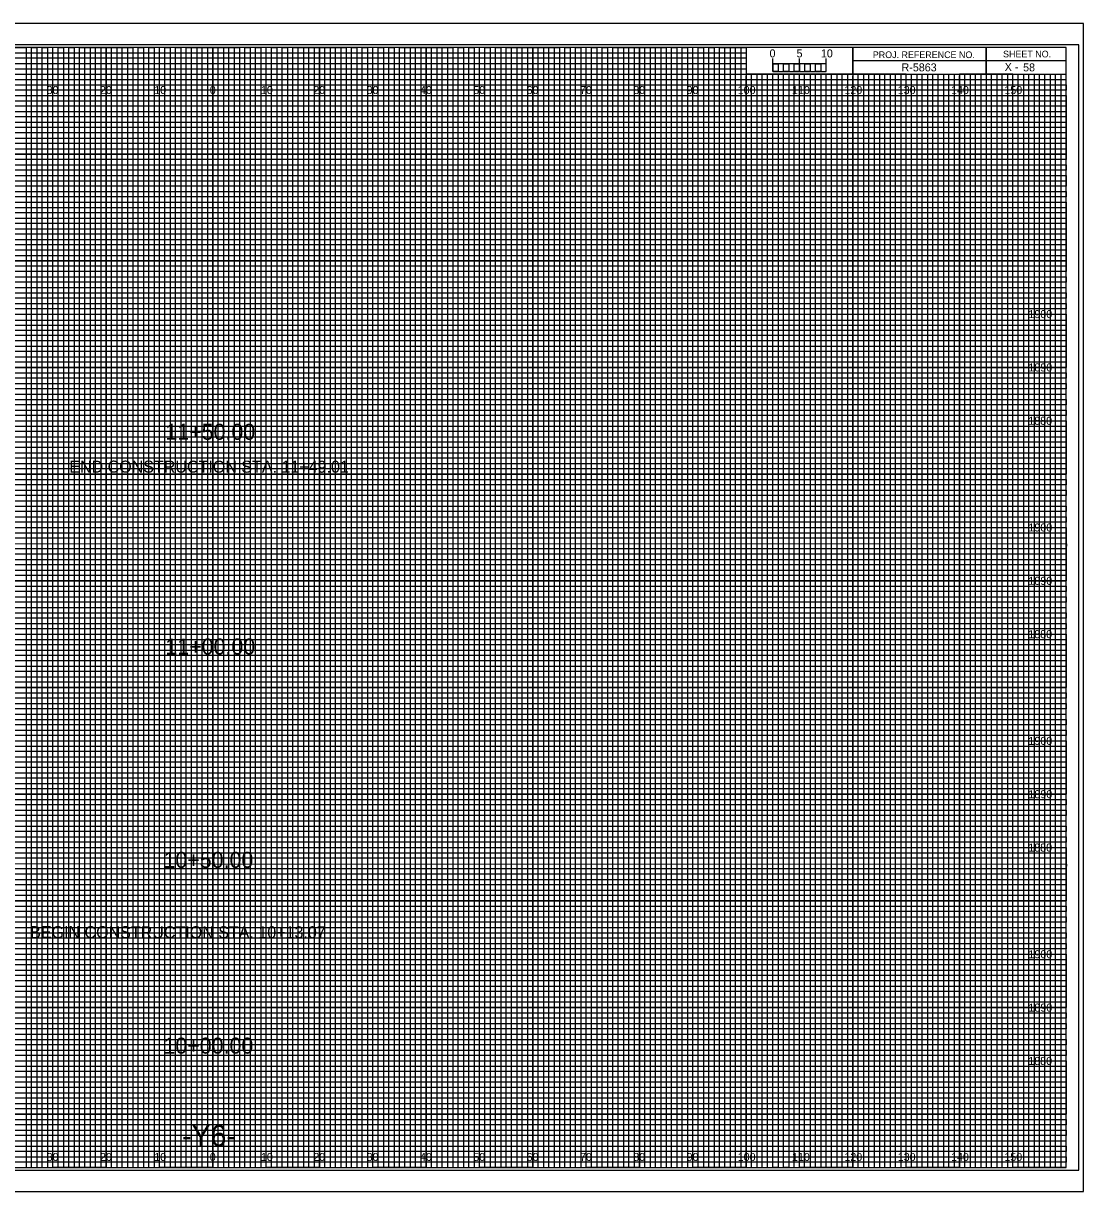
# Model space of a CAD drawing. Extents: x -13 to 323, y -4 to 214.
# Drawn here: x 124.5 to 323.3, y -4.5 to 214.5 of the extents above; entities that cross this region are included whole.
import ezdxf

# ---------------------------------------------------------------- set-up
doc = ezdxf.new("R2010")
doc.units = 0
for name, color, linetype in [('Prop XS Alignment Label', 7, 'Continuous'), ('Prop XS Bar Scale Labels', 7, 'Continuous'), ('Prop XS Elevation Labels', 7, 'Continuous'), ('Prop XS Offset Labels', 7, 'Continuous'), ('Prop XS Project Number', 7, 'Continuous'), ('Prop XS SE Text', 7, 'Continuous'), ('Prop XS Sheet Number', 7, 'Continuous'), ('Prop XS Station Labels', 7, 'Continuous'), ('Sheet Cross Section CELL', 7, 'Continuous'), ('Sheet Cross Section Grid Major CELL', 7, 'Continuous'), ('Sheet Cross Section Grid Middle CELL', 7, 'Continuous'), ('Sheet Cross Section Grid Minor 1 CELL', 7, 'Continuous'), ('Sheet Cross Section Grid Minor 2 CELL', 7, 'Continuous'), ('Sheet Cross Section Scale CELL', 7, 'Continuous'), ('Sheet Cutting Line CELL', 7, 'Continuous'), ('Sheet DOT Grid CELL', 7, 'Continuous'), ('Sheet Plot Border Inside CELL', 7, 'Continuous'), ('Sheet Plot Border Outside CELL', 7, 'Continuous')]:
    doc.layers.add(name, color=color, linetype=linetype)

msp = doc.modelspace()

# ---------------------------------------------------------------- linework, layer by layer
at = {"layer": 'Sheet Cross Section CELL'}
for p, q in [((305, 210), (305, 205)), ((305, 205), (305, 210)), ((280, 207.5), (280, 205)), ((320, 207.49), (280, 207.49)), ((280, 205), (320, 205))]:
    msp.add_line(p, q, dxfattribs=at)
for points in [[(320, 210), (0, 210), (0, 0), (320, 0)], [(280, 210), (260, 210), (260, 205.03), (280, 205.03)], [(320, 210), (280, 210), (280, 205), (320, 205)]]:
    msp.add_lwpolyline(points, close=True, dxfattribs=at)
at = {"layer": 'Sheet Cross Section Grid Major CELL'}
for p, q in [((130, 210), (120, 210)), ((130, 0), (130, 210)), ((150, 210), (140, 210)), ((140, 210), (140, 0)), ((150, 0), (150, 210)), ((170, 210), (160, 210)), ((160, 210), (160, 0)), ((170, 0), (170, 210)), ((190, 210), (180, 210)), ((180, 210), (180, 0)), ((190, 0), (190, 210)), ((210, 210), (200, 210)), ((200, 210), (200, 0)), ((210, 0), (210, 210)), ((230, 210), (220, 210)), ((220, 210), (220, 0)), ((230, 0), (230, 210)), ((250, 210), (240, 210)), ((240, 210), (240, 0)), ((250, 0), (250, 210)), ((260, 210), (260, 0)), ((270, 0), (270, 205)), ((290, 205), (280, 205)), ((280, 205), (280, 0)), ((290, 0), (290, 205)), ((310, 205), (300, 205)), ((300, 205), (300, 0)), ((310, 0), (310, 205)), ((140, 0), (130, 0)), ((160, 0), (150, 0)), ((180, 0), (170, 0)), ((200, 0), (190, 0)), ((220, 0), (210, 0)), ((240, 0), (230, 0)), ((260, 0), (250, 0)), ((280, 0), (270, 0)), ((300, 0), (290, 0)), ((320, 0), (310, 0)), ((320, 0), (320, 0))]:
    msp.add_line(p, q, dxfattribs=at)
for points in [[(0, 200), (320, 200), (320, 190), (0, 190)], [(0, 180), (320, 180), (320, 170), (0, 170)], [(0, 160), (320, 160), (320, 150), (0, 150)], [(0, 140), (320, 140), (320, 130), (0, 130)], [(0, 120), (320, 120), (320, 110), (0, 110)], [(0, 100), (320, 100), (320, 90), (0, 90)], [(0, 80), (320, 80), (320, 70), (0, 70)], [(0, 60), (320, 60), (320, 50), (0, 50)], [(0, 40), (320, 40), (320, 30), (0, 30)], [(0, 20), (320, 20), (320, 10), (0, 10)]]:
    msp.add_lwpolyline(points, dxfattribs=at)
at = {"layer": 'Sheet Cross Section Grid Middle CELL'}
for points in [[(115, 210), (125, 210), (125, 0), (135, 0), (135, 210), (145, 210), (145, 0), (155, 0), (155, 210), (165, 210), (165, 0), (175, 0), (175, 210), (185, 210), (185, 0), (195, 0), (195, 210), (205, 210), (205, 0), (215, 0), (215, 210), (225, 210), (225, 0), (235, 0), (235, 210), (245, 210), (245, 0), (255, 0), (255, 210), (259.93, 210), (260, 210), (260, 205), (264.99, 205), (264.99, 0), (275, 0), (275, 205), (285, 205), (285, 0), (295, 0), (295, 205), (305, 205), (305, 0), (315, 0), (315, 205)], [(0, 205), (275, 205)], [(0, 185), (320, 185), (320, 195), (0, 195)], [(0, 165), (320, 165), (320, 175), (0, 175)], [(0, 145), (320, 145), (320, 155), (0, 155)], [(0, 125), (320, 125), (320, 135), (0, 135)], [(0, 105), (320, 105), (320, 115), (0, 115)], [(0, 85), (320, 85), (320, 95), (0, 95)], [(0, 65), (320, 65), (320, 75), (0, 75)], [(0, 45), (320, 45), (320, 55), (0, 55)], [(0, 25), (320, 25), (320, 35), (0, 35)], [(0, 5), (320, 5), (320, 15), (0, 15)]]:
    msp.add_lwpolyline(points, dxfattribs=at)
at = {"layer": 'Sheet Cross Section Grid Minor 1 CELL'}
for p, q in [((0, 209), (260, 209)), ((260, 209), (260, 207.98)), ((260, 207.98), (0, 207.98)), ((0, 207), (260, 207)), ((260, 205.89), (0, 205.89)), ((260, 207), (260, 205.89)), ((0, 204), (320, 204))]:
    msp.add_line(p, q, dxfattribs=at)
for points in [[(0, 203), (270, 203), (320, 203), (320, 202), (0, 202)], [(0, 201), (320, 201), (320, 199), (0, 199)], [(0, 198), (320, 198), (320, 197), (0, 196.98)], [(0, 196), (320, 196), (320, 194), (0, 194)], [(0, 193), (320, 193), (320, 192), (0, 192)], [(0, 191), (320, 191), (320, 189), (0, 189)], [(0, 188), (320, 188), (320, 187), (0, 187)], [(0, 186), (320, 186), (320, 184), (0, 184)], [(0, 183), (320, 183), (320, 182), (0, 182)], [(0, 181), (320, 181), (320, 179), (0, 179)], [(0, 178), (320, 178), (320, 177), (0, 177)], [(0, 176), (320, 176), (320, 173.95), (320, 173), (320, 172), (0, 172)], [(0, 174), (320, 174), (320, 173), (0, 173)], [(0, 171), (320, 171), (320, 169), (0, 169.03)], [(0, 169.03), (320, 169), (320, 168), (0, 168)], [(0, 167), (320, 167), (320, 166), (0, 166)], [(0, 164), (320, 164), (320, 163), (0, 163)], [(0, 162), (320, 162), (320, 161), (0, 161)], [(-0.07, 158.89), (320, 158.89), (320, 157.88), (-0.07, 157.88)], [(0, 157), (320, 157), (320, 156), (0, 156)], [(0, 154), (320, 154), (320, 153), (0, 153)], [(0, 152), (320, 152), (320, 151), (0, 151)], [(0, 149), (320, 149), (320, 148), (0, 148)], [(0, 147), (320, 147), (320, 146), (0, 146)], [(0, 144), (320, 144), (320, 143), (0, 143)], [(0, 142), (320, 142), (320, 141), (0, 141)], [(0, 139), (320, 139), (319.99, 137.98), (0, 138)], [(0, 137), (320, 137), (320, 136), (0, 136)], [(0, 134), (320, 134), (320, 133), (0, 133)], [(0, 132), (320, 132), (320, 131), (0, 131)], [(0, 129), (320, 129), (320, 128), (0, 128)], [(0, 127), (320, 127), (320, 126), (0, 126)], [(0, 124), (320, 124), (320, 123), (0, 123)], [(0, 122), (320, 122), (320, 121), (0, 121)], [(0, 119), (320, 119), (320, 118), (0, 118)], [(0, 116.99), (320.07, 116.91), (320, 116), (0, 116)], [(0, 114), (320, 114), (320, 113), (0, 113)], [(0, 112), (320, 112), (320, 111), (0, 111)], [(0, 109), (320, 109), (320, 108), (0, 108)], [(0, 107), (320, 107), (320, 106), (0, 106)], [(0, 104), (320, 104), (320, 103), (0, 103)], [(0, 102), (320, 102), (320, 101), (0, 101)], [(0, 99), (320, 99), (320, 98), (0, 98)], [(0, 97), (320, 97), (320, 96), (0, 96)], [(0, 94), (320, 94), (320, 93), (0, 93)], [(0, 92), (320, 92), (320, 91), (0, 91)], [(0, 89), (320, 89), (320, 88), (0, 88)], [(0, 87), (320, 87), (320, 86), (0, 86)], [(0, 84), (320, 84), (320, 83), (0, 83)], [(0, 82), (320, 82), (320, 81), (0, 81)], [(0, 79), (320, 79), (319.99, 77.98), (0, 78)], [(0, 77), (320, 77), (320, 76), (0, 76)], [(0, 74), (320, 74), (320, 73), (0, 73)], [(0, 72), (320, 72), (320, 71), (0, 71)], [(0, 69), (320, 69), (320, 68), (0, 68)], [(0, 67), (320, 67), (320, 66), (0, 66)], [(0, 64), (320, 64), (320, 63), (0, 63)], [(0, 62), (320, 62), (320, 61), (0, 61)], [(0, 59), (320, 59), (320, 58), (0, 58)], [(0, 56.99), (320.07, 56.91), (320, 56), (0, 56)], [(0, 54), (320, 54), (320, 53), (0, 53)], [(0, 52), (320, 52), (320, 51), (0, 51)], [(0, 49), (320, 49), (320, 48), (0, 48)], [(0, 47), (320, 47), (320, 46), (0, 46)], [(0, 44), (320, 44), (320, 43), (0, 43)], [(0, 42), (320, 42), (320, 41), (0, 41)], [(0, 39), (320, 39), (320, 38), (0, 38)], [(0, 37), (320, 37), (320, 36), (0, 36)], [(0, 34), (320, 34), (320, 33), (0, 33)], [(0, 32), (320, 32), (320, 31), (0, 31)], [(0, 29), (320, 29), (320, 28), (0, 28)], [(0, 27), (320, 27), (320, 26), (0, 26)], [(0, 24), (320, 24), (320, 23), (0, 23)], [(0, 22), (320, 22), (320, 21), (0, 21)], [(0, 19), (320, 19), (320, 18), (0, 18)], [(0, 17), (320, 17), (320, 16), (0, 16)], [(0, 14), (320, 14), (320, 13), (0, 13)], [(0, 12), (320, 12), (320, 11), (0, 11)], [(0, 9), (320, 9), (320, 8), (0, 8)], [(0, 7), (320, 7), (320, 6), (0, 6)], [(0, 4), (320, 4), (320, 3), (0, 3)], [(0, 2), (320, 2), (320, 1), (0, 1)]]:
    msp.add_lwpolyline(points, dxfattribs=at)
at = {"layer": 'Sheet Cross Section Grid Minor 2 CELL'}
for p, q in [((267, 205), (266.01, 205)), ((266.01, 205), (266.01, 0)), ((267, 0), (267, 205)), ((269, 205), (268, 205)), ((268, 205), (268, 0)), ((269, 0), (269, 205)), ((266.01, 0), (265, 0)), ((268, 0), (267, 0))]:
    msp.add_line(p, q, dxfattribs=at)
for points in [[(125, 0), (126, 0), (126, 210), (127, 210), (127, 0)], [(127, 0), (128, 0), (128, 210), (129, 210), (129, 0)], [(130, 0), (131, 0), (131, 210), (132, 210), (132, 0)], [(132, 0), (133, 0), (133, 210), (134, 210), (134, 0)], [(135, 0), (136, 0), (136, 210), (137, 210), (137, 0)], [(137, 0), (138, 0), (138, 210), (139, 210), (139, 0)], [(140, 0), (141, 0), (141, 210), (142, 210), (142, 0)], [(142, 0), (143, 0), (143, 210), (144, 210), (144, 0)], [(145, 0), (146, 0), (146, 210), (147, 210), (147, 0)], [(147, 0), (148, 0), (148, 210), (149, 210), (149, 0)], [(150, 0), (151, 0), (151, 210), (152, 210), (152, 0)], [(152, 0), (153, 0), (153, 210), (154, 210), (154, 0)], [(155, 0), (156, 0), (156, 210), (157, 210), (157, 0)], [(157, 0), (158, 0), (158, 210), (159, 210), (159, 0)], [(160, 0), (161, 0), (161, 210), (162, 210), (162, 0)], [(162, 0), (163, 0), (163, 210), (164, 210), (164, 0)], [(165, 0), (166, 0), (166, 210), (167, 210), (167, 0)], [(167, 0), (168, 0), (168, 210), (169, 210), (169, 0)], [(170, 0), (171, 0), (171, 210), (172, 210), (172, 0)], [(172, 0), (173, 0), (173, 210), (174, 210), (174, 0)], [(175, 0), (176, 0), (176, 210), (177, 210), (177, 0)], [(177, 0), (178, 0), (178, 210), (179, 210), (179, 0)], [(180, 0), (181, 0), (181, 210), (182, 210), (182, 0)], [(182, 0), (183, 0), (183, 210), (184, 210), (184, 0)], [(185, 0), (186, 0), (186, 210), (187, 210), (187, 0)], [(187, 0), (188, 0), (188, 210), (189, 210), (189, 0)], [(190, 0), (191, 0), (191, 210), (192, 210), (192, 0)], [(192, 0), (193, 0), (193, 210), (194, 210), (194, 0)], [(195, 0), (196, 0), (196, 210), (197, 210), (197, 0)], [(197, 0), (198, 0), (198, 210), (199, 210), (199, 0)], [(200, 0), (201, 0), (201, 210), (202, 210), (202, 0)], [(202, 0), (203, 0), (203, 210), (204, 210), (204, 0)], [(205, 0), (206, 0), (206, 210), (207, 210), (207, 0)], [(207, 0), (208, 0), (208, 210), (209, 210), (209, 0)], [(210, 0), (211, 0), (211, 210), (212, 210), (212, 0)], [(212, 0), (213, 0), (213, 210), (214, 210), (214, 0)], [(215, 0), (216, 0), (216, 210), (217, 210), (217, 0)], [(217, 0), (218, 0), (218, 210), (219, 210), (219, 0)], [(220, 0), (221, 0), (221, 210), (222, 210), (222, 0)], [(222, 0), (223, 0), (223, 210), (224, 210), (224, 0)], [(225, 0), (226, 0), (226, 210), (227, 210), (227, 0)], [(227, 0), (228, 0), (228, 210), (229, 210), (229, 0)], [(230, 0), (231, 0), (231, 210), (232, 210), (232, 0)], [(232, 0), (233, 0), (233, 210), (234, 210), (234, 0)], [(235, 0), (236, 0), (236, 210), (237, 210), (237, 0)], [(237, 0), (238, 0), (238, 210), (239, 210), (239, 0)], [(240, 0), (241, 0), (241, 210), (242, 210), (242, 0)], [(242, 0), (243, 0), (243, 210), (244, 210), (244, 0)], [(245, 0), (246, 0), (246, 210), (247, 210), (247, 0)], [(247, 0), (248, 0), (248, 210), (249, 210), (249, 0)], [(250, 0), (251, 0), (251, 210), (252, 210), (252, 0)], [(252, 0), (253, 0), (253, 210), (254, 210), (254, 0)], [(255, 0), (256, 0), (256, 210), (257, 210), (257, 0)], [(257, 0), (258, 0), (258, 210), (259, 210), (259, 0)], [(260, 0), (261, 0), (261, 205), (262.02, 205), (262.02, 0)], [(262, 0), (263, 0), (263, 205), (263.99, 205), (263.99, 0)], [(270, 0), (270.98, 0), (270.98, 205), (272, 205), (272, 0)], [(272, 0), (273, 0), (273, 205), (274.05, 205), (274.05, 0)], [(275, 0), (276, 0), (276, 205), (277, 205), (277, 0)], [(277, 0), (278, 0), (278, 205), (279, 205), (279, 0)], [(280, 0), (281, 0), (281, 205), (282, 205), (282, 0)], [(282, 0), (283, 0), (283, 205), (284, 205), (284, 0)], [(285, 0), (286, 0), (286, 205), (287, 205), (287, 0)], [(287, 0), (288, 0), (288, 205), (289, 205), (289, 0)], [(290, 0), (291, 0), (291, 205), (292, 205), (292, 0)], [(292, 0), (293, 0), (293, 205), (294, 205), (294, 0)], [(295, 0), (296, 0), (296, 205), (297, 205), (297, 0)], [(297, 0), (298, 0), (298, 205), (299, 205), (299, 0)], [(300, 0), (301, 0), (301, 205), (302, 205), (302, 0)], [(302, 0), (303, 0), (303, 205), (304, 205), (304, 0)], [(305, 0), (306, 0), (306, 205), (307, 205), (307, 0)], [(307, 0), (308, 0), (308, 205), (309, 205), (309, 0)], [(310, 0), (311, 0), (311, 205), (312, 205), (312, 0)], [(312, 0), (313, 0), (313, 205), (314, 205), (314, 0)], [(315, 0), (316, 0), (316, 205), (317, 205), (317, 0)], [(317, 0), (318, 0), (318, 205), (319, 205), (319, 0)]]:
    msp.add_lwpolyline(points, dxfattribs=at)
at = {"layer": 'Sheet Cross Section Scale CELL'}
for p, q in [((265, 205.49), (265, 207.9)), ((265, 206.9), (265, 207.9)), ((270, 205.49), (270, 207.9)), ((275, 205.49), (275, 207.9)), ((275, 206.9), (275, 207.9))]:
    msp.add_line(p, q, dxfattribs=at)
for points in [[(275, 206.9), (265, 206.9), (265, 205.49), (275, 205.49)], [(265, 206.9), (266, 206.9), (266, 205.49), (265, 205.49)], [(267, 206.9), (268, 206.9), (268, 205.49), (267, 205.49)], [(269, 206.9), (270, 206.9), (270, 205.49), (269, 205.49)], [(271, 206.9), (272, 206.9), (272, 205.49), (271, 205.49)], [(273, 206.9), (274, 206.9), (274, 205.49), (273, 205.49)]]:
    msp.add_lwpolyline(points, close=True, dxfattribs=at)
at = {"layer": 'Sheet Cutting Line CELL'}
for p, q in [((323.3, 214.5), (-13.4, 214.5)), ((-13.4, -4.5), (323.3, -4.5))]:
    msp.add_line(p, q, dxfattribs=at)
at = {"layer": 'Sheet DOT Grid CELL'}
for p, q in [((130, 0), (130, 210)), ((140, 0), (140, 210)), ((150, 0), (150, 210)), ((160, 0), (160, 210)), ((170, 0), (170, 210)), ((180, 0), (180, 210)), ((190, 0), (190, 210)), ((200, 0), (200, 210)), ((210, 0), (210, 210)), ((220, 0), (220, 210)), ((230, 0), (230, 210)), ((240, 0), (240, 210)), ((250, 0), (250, 210)), ((260, 0), (260, 204.69)), ((270, 0), (270, 204.69)), ((280, 0), (280, 204.69)), ((290, 0), (290, 204.69)), ((300, 0), (300, 204.69)), ((310, 0), (310, 204.69)), ((0, 200), (320, 200)), ((0, 190), (320, 190)), ((0, 180), (320, 180)), ((0, 170), (320, 170)), ((0, 160), (320, 160)), ((0, 150), (320, 150)), ((0, 140), (320, 140)), ((0, 130), (320, 130)), ((0, 120), (320, 120)), ((0, 110), (320, 110)), ((0, 100), (320, 100)), ((0, 90), (320, 90)), ((0, 80), (320, 80)), ((0, 70), (320, 70)), ((0, 60), (320, 60)), ((0, 50), (320, 50)), ((0, 40), (320, 40)), ((0, 30), (320, 30)), ((0, 20), (320, 20)), ((0, 10), (320, 10))]:
    msp.add_line(p, q, dxfattribs=at)
at = {"layer": 'Sheet Plot Border Inside CELL'}
msp.add_lwpolyline([(-10.8, -0.5), (322.4, -0.5), (322.4, 210.5), (-10.8, 210.5)], close=True, dxfattribs=at)
at = {"layer": 'Sheet Plot Border Outside CELL'}
msp.add_lwpolyline([(-13.4, -4.5), (323.3, -4.5), (323.3, 214.5), (-13.4, 214.5)], close=True, dxfattribs=at)

# ---------------------------------------------------------------- texts
at = {"layer": 'Prop XS Alignment Label'}
msp.add_text('-Y6-', height=4, dxfattribs=at).set_placement((154.25, 4))
at = {"layer": 'Prop XS Bar Scale Labels'}
for s, p in [('5', (269.47, 208.12)), ('10', (274.04, 208.12))]:
    msp.add_text(s, height=1.5, dxfattribs=at).set_placement(p)
at = {"layer": 'Prop XS Elevation Labels'}
for s, p in [('1900', (312.95, 159.25)), ('1890', (312.95, 149.25)), ('1880', (312.92, 139.25)), ('1900', (312.95, 119.25)), ('1890', (312.95, 109.25)), ('1880', (312.92, 99.25)), ('1900', (312.95, 79.25)), ('1890', (312.95, 69.25)), ('1880', (312.92, 59.25)), ('1900', (312.95, 39.25)), ('1890', (312.95, 29.25)), ('1880', (312.92, 19.25))]:
    msp.add_text(s, height=1.5, dxfattribs=at).set_placement(p)
at = {"layer": 'Prop XS Offset Labels'}
for s, p in [('30', (128.86, 201.25)), ('20', (138.86, 201.25)), ('10', (149.04, 201.25)), ('0', (159.45, 201.25)), ('0', (159.45, 201.25)), ('10', (169.04, 201.25)), ('20', (178.86, 201.25)), ('30', (188.86, 201.25)), ('40', (198.86, 201.25)), ('50', (208.86, 201.25)), ('60', (218.86, 201.25)), ('70', (228.86, 201.25)), ('80', (238.86, 201.25)), ('90', (248.86, 201.25)), ('100', (258.44, 201.25)), ('110', (268.62, 201.25)), ('120', (278.44, 201.25)), ('130', (288.44, 201.25)), ('140', (298.44, 201.25)), ('150', (308.44, 201.25)), ('30', (128.86, 1.25)), ('20', (138.86, 1.25)), ('10', (149.04, 1.25)), ('0', (159.45, 1.25)), ('0', (159.45, 1.25)), ('10', (169.04, 1.25)), ('20', (178.86, 1.25)), ('30', (188.86, 1.25)), ('40', (198.86, 1.25)), ('50', (208.86, 1.25)), ('60', (218.86, 1.25)), ('70', (228.86, 1.25)), ('80', (238.86, 1.25)), ('90', (248.86, 1.25)), ('100', (258.44, 1.25)), ('110', (268.62, 1.25)), ('120', (278.44, 1.25)), ('130', (288.44, 1.25)), ('140', (298.44, 1.25)), ('150', (308.44, 1.25))]:
    msp.add_text(s, height=1.5, dxfattribs=at).set_placement(p)
at = {"layer": 'Prop XS Project Number'}
msp.add_text('R-5863', height=1.5, dxfattribs=at).set_placement((289.16, 205.5))
at = {"layer": 'Prop XS SE Text'}
for s, p in [('END CONSTRUCTION STA. 11+49.01', (133.11, 130.29)), ('BEGIN CONSTRUCTION STA. 10+13.07', (125.77, 43.02))]:
    msp.add_text(s, height=2.25, rotation=359.9687, dxfattribs=at).set_placement(p)
at = {"layer": 'Prop XS Sheet Number'}
msp.add_text('58', height=1.5, dxfattribs=at).set_placement((311.95, 205.5))
at = {"layer": 'Prop XS Station Labels'}
for s, p in [('11+50.00', (151.13, 136.44)), ('11+00.00', (151.13, 96.18)), ('10+50.00', (150.77, 56.19)), ('10+00.00', (150.77, 21.37))]:
    msp.add_text(s, height=3, dxfattribs=at).set_placement(p)
at = {"layer": 'Sheet Cross Section CELL'}
for s, height, p in [('PROJ. REFERENCE NO.', 1.25, (283.77, 207.99)), ('SHEET NO.', 1.25, (308.19, 208.12)), ('X -    ', 1.5, (308.5, 205.58))]:
    msp.add_text(s, height=height, dxfattribs=at).set_placement(p)
at = {"layer": 'Sheet Cross Section Scale CELL'}
msp.add_text('0', height=1.5, dxfattribs=at).set_placement((264.41, 208.12))

doc.saveas('drawing.dxf')
